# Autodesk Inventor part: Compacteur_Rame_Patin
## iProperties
Created: 2008-12
Part Number: Compacteur_Rame_Patin
Document SubType Name: Modeling
Designer: claivier
Author: claivier
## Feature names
1. Extrusion1
2. Perçage1 [Hole]
